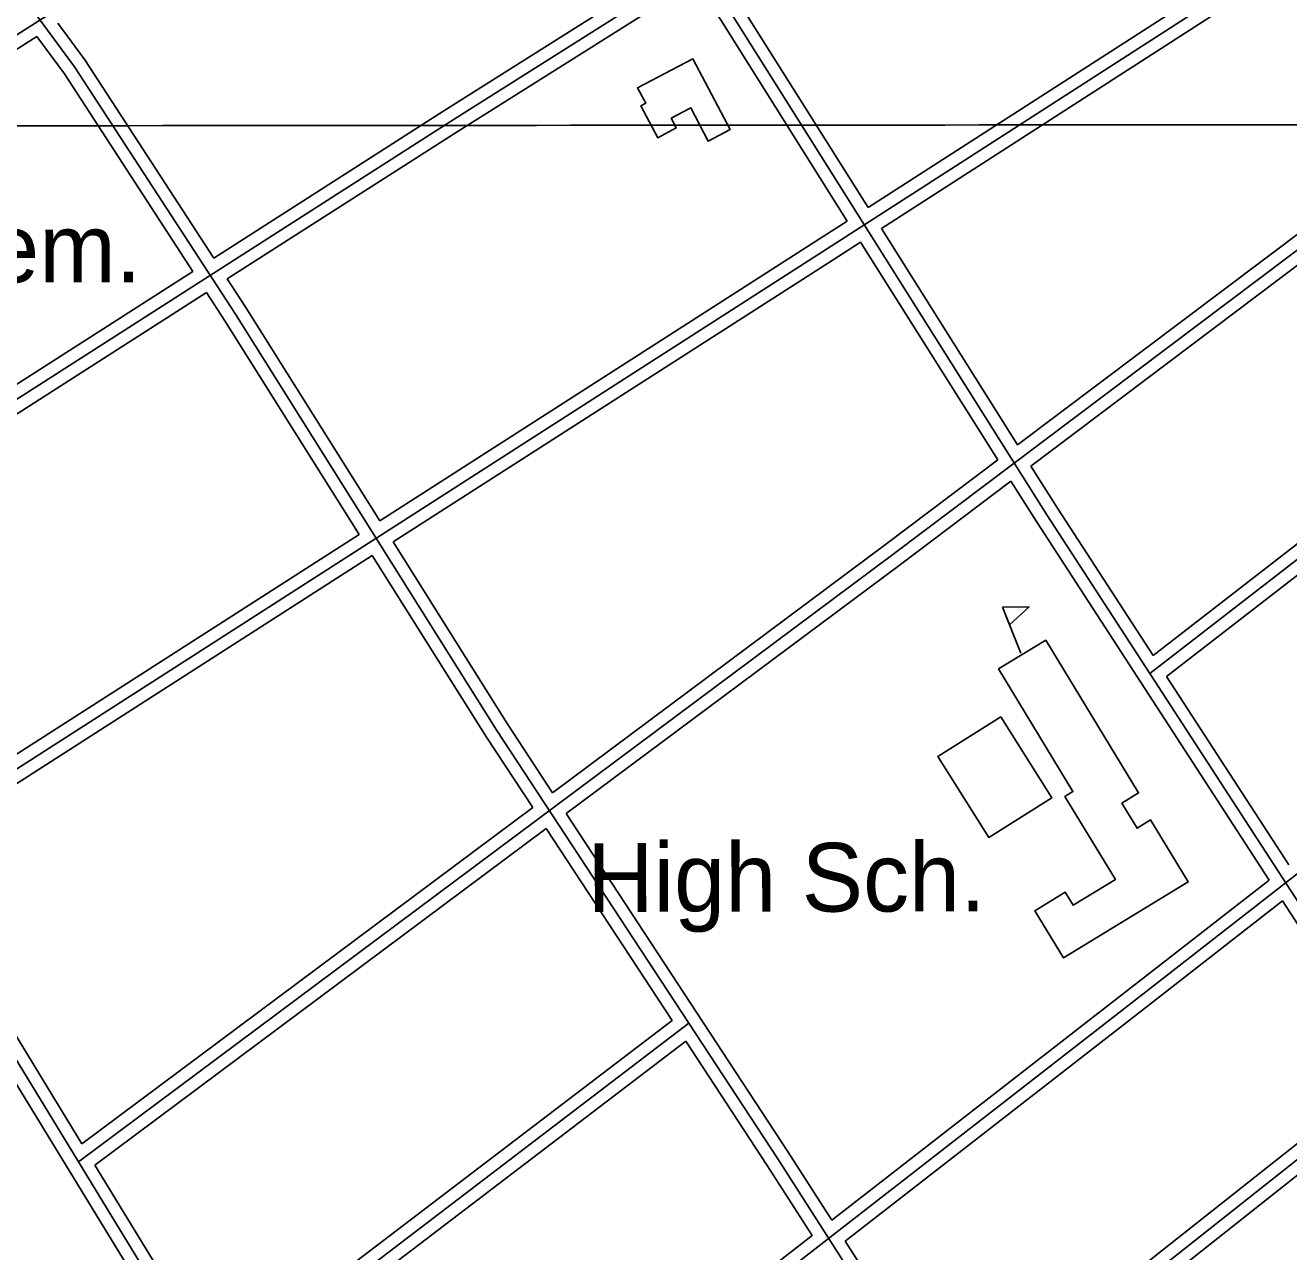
# Model space of a CAD drawing. Extents: x 3297772 to 3335630, y 634068 to 659439.
# Drawn here: x 3310382 to 3311908, y 647184 to 648666 of the extents above; entities that cross this region are included whole.
import ezdxf

# ---------------------------------------------------------------- set-up
doc = ezdxf.new("R2010")
doc.units = 0
for name, color, linetype in [('V-BLDG-IDEN', 7, 'Continuous'), ('V-BLDG-OTLN', 7, 'Continuous'), ('V-GRID-MAJR', 7, 'Continuous'), ('V-ROAD-CNTR', 7, 'Continuous'), ('V-SITE-OTLN-IDEN', 7, 'Continuous')]:
    doc.layers.add(name, color=color, linetype=linetype)

msp = doc.modelspace()

# ---------------------------------------------------------------- linework, layer by layer
at = {"layer": 'V-BLDG-OTLN'}
msp.add_line((3311584.4220000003, 647907.196), (3311562.122, 647962.898), dxfattribs=at)
for points in [[(3311188.0725864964, 648625.5557221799), (3311233.1154964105, 648540.094893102), (3311206.4555497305, 648526.0439212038), (3311185.402591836, 648565.9898413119), (3311161.847638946, 648553.57586614), (3311167.9846266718, 648541.931889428), (3311145.526671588, 648530.0949131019), (3311125.268712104, 648568.529836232), (3311131.111700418, 648571.6088300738), (3311121.241720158, 648590.336792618)], [(3311562.122, 647962.898), (3311594.2660000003, 647963.324), (3311570.708, 647941.451)], [(3311557.2190000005, 647888.2179999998), (3311647.1340000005, 647740.0949999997), (3311637.5230000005, 647734.2609999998), (3311698.5560000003, 647633.7149999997), (3311647.5280000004, 647602.7399999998), (3311637.9540000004, 647618.5109999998), (3311601.1860000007, 647596.1899999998), (3311635.6540000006, 647539.4119999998), (3311786.4770000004, 647630.9719999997), (3311741.0590000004, 647705.7869999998), (3311724.6710000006, 647695.8379999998), (3311706.2550000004, 647726.1729999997), (3311726.4320000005, 647738.4219999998), (3311614.4150000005, 647922.9399999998)], [(3311560.1790000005, 647830.323), (3311621.5770000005, 647732.441), (3311545.4480000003, 647684.688), (3311484.0500000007, 647782.571)]]:
    msp.add_lwpolyline(points, close=True, dxfattribs=at)
at = {"layer": 'V-GRID-MAJR'}
msp.add_spline([(3301875.511, 648538.54), (3307136.054, 648541.983), (3312396.597, 648546.191), (3317657.139, 648551.165), (3322917.681, 648556.903), (3328178.222, 648563.407), (3333438.761, 648570.676), (3333438.762, 648570.676)], degree=3, dxfattribs=at)
at = {"layer": 'V-ROAD-CNTR'}
for points in [[(3310445.758071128, 647292.56838816), (3311429.686103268, 648026.5969201), (3312387.1281883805, 648747.63047803), (3313151.293660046, 649327.1443190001), (3313650.767661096, 649696.2965806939), (3313656.3186499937, 649702.6975678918), (3313657.4956476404, 649707.1285590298), (3313654.611653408, 649713.2485467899), (3313412.689137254, 650029.13291502), (3313159.269644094, 650380.9602113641), (3312980.819000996, 650650.2736727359), (3312864.083234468, 650845.3942824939), (3312685.676591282, 651166.863639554), (3312552.8778568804, 651454.028065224), (3312411.314140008, 651779.201414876), (3312404.497153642, 651786.75939976), (3312395.49317165, 651789.9943932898), (3312011.430939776, 651624.287724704), (3311864.8772328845, 651538.0548971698), (3311646.3846698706, 651445.3270826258)], [(3313326.0353105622, 650149.436674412), (3312559.07284449, 649661.2426508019), (3312271.130420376, 649481.9440093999), (3311691.5125796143, 649052.7308678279), (3310895.1911722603, 648549.8458736), (3310014.446933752, 647985.7830017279)], [(3312538.3908858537, 648862.342248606), (3312246.516469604, 649205.222562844), (3311949.495063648, 649557.7548577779), (3311933.901094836, 649569.93883341), (3311922.9381167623, 649576.9168194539), (3311909.680143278, 649578.560816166), (3311892.29917804, 649578.365816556), (3311870.545221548, 649576.1998208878), (3311806.407349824, 649556.6208600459), (3311715.9435307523, 649509.5969540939), (3309918.72812519, 648366.885239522), (3308700.572561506, 647622.2597287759), (3307816.6983292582, 647071.6478300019), (3307154.2246542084, 646652.5346682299)], [(3311916.532129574, 646572.908827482), (3310815.6463313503, 645684.799603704), (3310810.46634171, 645685.5856021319), (3310806.1543503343, 645687.143599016), (3310631.085700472, 645882.5712081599), (3310630.612701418, 645887.728197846), (3310631.81669901, 645897.5761781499), (3311582.242798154, 646664.2096448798), (3312459.8920428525, 647374.3182246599), (3313109.4397437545, 647904.976163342), (3313632.849696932, 648328.6143160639), (3314289.77938307, 648868.8572355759), (3314295.57937147, 648875.389222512), (3314300.6453613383, 648887.5761981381), (3314299.9833626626, 648896.13018103), (3314294.367373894, 648906.8611595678), (3314031.9168987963, 649256.505460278), (3314022.2139182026, 649263.506446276), (3314012.0339385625, 649268.987435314), (3314003.5029556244, 649267.0664391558), (3313990.6229813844, 649261.91444946), (3312843.9892746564, 648362.4012484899), (3311728.172506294, 647492.684987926), (3310776.372409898, 646752.8044676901)], [(3309332.607297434, 649073.7878257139), (3309580.2998020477, 648676.4496203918), (3309993.824974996, 648018.6889359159), (3310323.404315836, 647492.783987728), (3310571.268820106, 647087.1877989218), (3310807.283348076, 646702.4105684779), (3311025.519911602, 646366.1832409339), (3311127.914706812, 646231.266510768), (3311267.169428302, 646051.4268704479)], [(3310992.331977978, 649049.507874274), (3311234.6884932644, 648679.832613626), (3311615.7517311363, 648074.3818245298), (3312000.2299621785, 647481.84300961), (3312316.86332891, 646995.2549827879), (3312636.259690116, 646495.491982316)], [(3310178.165606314, 648994.1209850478), (3310348.311266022, 648741.4214904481), (3310441.086080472, 648615.774741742), (3310635.325691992, 648316.8963395), (3310951.2520601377, 647814.0453452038), (3311290.506381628, 647296.382380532), (3311523.6179154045, 646932.337108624), (3311656.765649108, 646724.506524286)], [(3310214.2215342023, 647667.0056392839), (3311349.299264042, 648395.2291828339), (3311939.060084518, 648775.247422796)], [(3311399.817163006, 648445.625082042), (3311918.336125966, 648779.737413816)], [(3311415.799131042, 648420.234132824), (3311934.566093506, 648754.5074642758)], [(3311174.643613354, 648744.063485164), (3310887.1411883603, 648562.502848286), (3310609.2577441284, 648384.535204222)], [(3311216.462529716, 648734.9915033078), (3311247.3094680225, 648687.94059741), (3311399.818163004, 648445.627082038)], [(3311191.094580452, 648718.971535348), (3310903.2411561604, 648537.1888989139), (3310625.605711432, 648359.3802545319)], [(3311191.093580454, 648718.971535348), (3311222.067518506, 648671.7246298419), (3311374.599213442, 648429.3761145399)], [(3310420.8821208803, 648668.391636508), (3310453.419055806, 648624.3247246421), (3310609.25674413, 648384.535204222)], [(3312752.8514569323, 648665.316642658), (3312046.505869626, 648119.8877335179), (3311740.230482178, 647882.5402082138)], [(3310395.504171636, 648652.254668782), (3309926.664109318, 648354.1562649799), (3309835.6252913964, 648298.5063762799)], [(3310395.504171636, 648652.254668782), (3310428.753105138, 648607.224758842), (3310583.9927946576, 648368.35623658)], [(3311580.32980198, 648158.822655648), (3312077.102808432, 648532.9329074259)], [(3311596.366769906, 648133.3427066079), (3312093.377775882, 648507.6339580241)], [(3310810.004342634, 648067.059839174), (3311341.187280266, 648407.8461575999), (3311374.598213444, 648429.375114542)], [(3311415.799131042, 648420.2361328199), (3311580.32980198, 648158.822655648)], [(3310825.965310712, 648041.655889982), (3311357.4112478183, 648382.6122080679), (3311390.5801814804, 648403.984165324)], [(3311390.5791814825, 648403.9851653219), (3311556.280850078, 648140.71169187)], [(3310583.9947946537, 648368.35623658), (3310019.1129244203, 648006.5839601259)], [(3310625.6047114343, 648359.3802545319), (3310647.965666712, 648324.9733233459), (3310810.0053426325, 648067.0608391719)], [(3310600.342761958, 648343.2002868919), (3310035.044892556, 647981.16201097)], [(3310600.340761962, 648343.2012868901), (3310622.6857172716, 648308.8193556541), (3310784.753393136, 648050.859871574)], [(3312236.675489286, 648285.685401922), (3312037.3278879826, 648131.75170979), (3311743.9354747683, 647904.3881645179)], [(3312253.0234565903, 648260.4064524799), (3312055.68385127, 648108.023757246), (3311760.323441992, 647879.1342150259)], [(3310932.7600971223, 646509.093955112), (3311764.5494335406, 647174.132625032), (3312442.7080772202, 647710.8625515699), (3312997.030968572, 648147.1516789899)], [(3311018.6049254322, 647738.636496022), (3311420.689121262, 648038.5998960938), (3311556.280850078, 648140.71169187)], [(3311596.366769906, 648133.3427066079), (3311628.391705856, 648082.4598083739), (3311743.9354747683, 647904.3881645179)], [(3311035.078892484, 647713.498546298), (3311438.683085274, 648014.5939441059), (3311572.317818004, 648115.23174283)], [(3311572.317818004, 648115.23174283), (3311603.1117564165, 648066.3038406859), (3311884.108194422, 647633.2467068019)], [(3310218.8805248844, 647687.8165976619), (3310784.753393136, 648050.8588715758)], [(3310825.965310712, 648041.6568899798), (3310963.877034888, 647822.147329), (3311018.6049254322, 647738.6374960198)], [(3310234.81249302, 647662.394648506), (3310800.714361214, 648025.4559223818)], [(3310800.7133612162, 648025.45692238), (3310938.627085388, 647805.943361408), (3310994.514973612, 647720.6655319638)], [(3311760.3224419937, 647879.1342150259), (3311907.858146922, 647651.759669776)], [(3310449.97706269, 647314.430344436), (3310994.514973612, 647720.6655319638)], [(3311035.078892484, 647713.4995462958), (3311303.09535645, 647304.53836422), (3311355.804251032, 647222.224528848)], [(3310465.68703127, 647288.7223958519), (3311010.9889406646, 647695.526582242)], [(3311010.9889406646, 647695.5275822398), (3311163.014636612, 647463.5540461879)], [(3310234.81249302, 647662.395648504), (3310336.1592903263, 647500.6779719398), (3310449.97706269, 647314.430344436)], [(3311884.10919442, 647633.2477068), (3311718.958524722, 647504.521964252), (3311355.8052510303, 647222.224528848)], [(3311900.5001616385, 647607.9867573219), (3311737.3864878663, 647480.8480116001), (3311372.0502185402, 647196.8545795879)], [(3311900.4981616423, 647607.9867573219), (3311987.6519873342, 647473.6700259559), (3312032.249898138, 647405.134163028)], [(3311183.217596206, 647460.092053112), (3310610.363741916, 647023.450926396)], [(3311163.014636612, 647463.5540461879), (3310614.4707337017, 647045.4418824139)], [(3311179.50060364, 647438.3980965), (3310630.23670217, 647019.737933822)], [(3311179.50060364, 647438.399096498), (3311277.9174068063, 647288.2263968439), (3311332.0192986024, 647203.735565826)], [(3310362.351237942, 647400.286172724), (3310531.1759002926, 647124.02872524)], [(3311506.4419497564, 646986.9739993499), (3311755.2114522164, 647185.871601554), (3312032.249898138, 647405.134163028)], [(3311522.708917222, 646961.5700501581), (3311773.8874148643, 647162.39364851), (3312048.681865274, 647379.8802135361)], [(3310465.6880312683, 647288.7223958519), (3310584.0617945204, 647095.019783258), (3310614.4717337, 647045.4418824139)], [(3311332.0202986, 647203.735565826), (3310780.397401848, 646774.932423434)], [(3311372.049218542, 647196.8545795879), (3311506.4429497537, 646986.9749993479)]]:
    msp.add_lwpolyline(points, dxfattribs=at)

# ---------------------------------------------------------------- texts
at = {"layer": 'V-BLDG-IDEN'}
msp.add_text('High Sch.', height=82.99983200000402, rotation=0.0733610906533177, dxfattribs=at).set_placement((3311060.5279459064, 647594.689574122))
at = {"layer": 'V-SITE-OTLN-IDEN'}
msp.add_text('Cem.', height=82.99983200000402, dxfattribs=at).set_placement((3310256.5119797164, 648355.2452628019))

doc.saveas('drawing.dxf')
